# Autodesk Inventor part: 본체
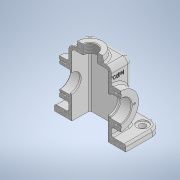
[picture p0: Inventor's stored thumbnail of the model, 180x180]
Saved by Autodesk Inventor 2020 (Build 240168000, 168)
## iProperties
Created: 2021-07
Part Number: 본체
Material: 일반
Document SubType Name: Modeling
Designer: Owner
Density: 1 g/cm^3
Appearance: 기본값
Mass: 278.252 g
Surface Area: 858.264 cm^2
Volume: 278.252 cm^3
Author: Owner
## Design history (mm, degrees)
sketch "스케치1"
  geometry: L1 (34, -34)-(-34, -34); L2 (-34, -34)-(-34, 34); L3 (-34, 34)-(34, 34); L4 (34, 34)-(34, -34); L5 (34, -34)-(-34, 34); L6 (-34, -34)-(34, 34); 1 further point
  constraints: 12 end point, 2 midpoint, 2 parallel, 1 horizontal, 1 perpendicular
  dimensions: "d0" = 68 distance of L2.end L3.end; "d1" = 68 distance of L1.end L2.end
extrude "돌출1" new body sketch "스케치1" distance "d2" = 105; taper "d3" = 0 deg
fillet "모깎기1" dims "d4" = 8
fillet "모깎기2" dims "d5" = 8
feature "쉘1" dims "d6" = 5
node "작업 평면1"
sketch "스케치2"
  geometry: C1 r 20 at (0, 0); 1 further point
  constraints: 1 centre point, 1 coincident
  dimensions: "d8" = 40 diameter of C1
extrude "돌출2" join sketch "스케치2" stored distance "d9" = 105; taper "d10" = 8 deg
sketch "스케치4"
  geometry: L1 (-57, -57)-(57, -57); L2 (57, -57)-(57, 57); L3 (57, 57)-(-57, 57); L4 (-57, 57)-(-57, -57); L5 (-57, -57)-(57, 57); L6 (57, -57)-(-57, 57); L7 (-26, 34)-(26, 34) reference; L8 (-34, -26)-(-34, 26) reference; L9 (26, -34)-(-26, -34) reference; L10 (34, 26)-(34, -26) reference; L11 (-26, 29)-(26, 29) reference; L12 (29, 26)-(29, -26) reference; L13 (26, -29)-(-26, -29) reference; L14 (-29, -26)-(-29, 26) reference; A1 r 8 centre (-26, 26) between (-26, 34) and (-34, 26) reference; A2 r 8 centre (-26, -26) between (-34, -26) and (-26, -34) reference; A3 r 8 centre (26, -26) between (26, -34) and (34, -26) reference; A4 r 8 centre (26, 26) between (34, 26) and (26, 34) reference; A5 r 3 centre (26, 26) between (29, 26) and (26, 29) reference; A6 r 3 centre (26, -26) between (26, -29) and (29, -26) reference; A7 r 3 centre (-26, -26) between (-29, -26) and (-26, -29) reference; A8 r 3 centre (-26, 26) between (-26, 29) and (-29, 26) reference; 1 further point
  constraints: 12 end point, 2 midpoint, 2 parallel, 1 horizontal, 1 perpendicular
  dimensions: "d11" = 114 distance of L3.end L2.end; "d12" = 114 distance of L2.end L1.end
extrude "돌출3" join sketch "스케치4" distance "d13" = 10; taper "d14" = 0 deg
node "작업 평면2"
sketch "스케치6"
  geometry: L1 (26, -97)-(26, 44.872); L2 (83, -97)-(-31, -97) reference; C1 r 28.5 at (26, -45)
  constraints: 2 end point, 1 centre point, 1 point on line, 1 vertical
  dimensions: "d20" = 57 diameter of C1; "d21" = 52 distance from line of L2 C1.centre
extrude "돌출5" join sketch "스케치6" stored distance "d22" = 15; taper "d23" = 0 deg
sketch "스케치7"
  geometry: C1 r 28.5 at (0, 0) reference; C2 r 17.5 at (0, 0); 1 further point
  constraints: 1 centre point, 1 coincident
  dimensions: "d24" = 35 diameter of C2
extrude "돌출6" cut sketch "스케치7" distance "d25" = 17; taper "d26" = 0 deg
sketch "스케치8"
  geometry: C1 r 17.5 at (0, 0) reference; C2 r 15 at (0, 0); 1 further point
  constraints: 1 centre point, 1 coincident
  dimensions: "d27" = 30 diameter of C2
extrude "돌출7" cut sketch "스케치8" distance "d28" = 3; taper "d29" = 0 deg
sketch "스케치9" dims "d30" = 44
  geometry: C1 r 28.5 at (0, 0) reference; C2 r 15 at (0, 0) reference; 3 further points
  constraints: 1 coincident, 1 vertical alignment, 2 other
hole "구멍1" sketch "스케치9" at (0, 22) diameter "d31" = 3.242; stored, may be unused: countersink angle "d35" = 90 deg, drill point angle "d37" = 118 deg; dims "d32" = 8, "d33" = 4, "d34" = 2, "d36" = 10
sketch "스케치10"
  geometry: C1 r 20 at (0, 0) reference; 1 further point
sketch "스케치11"
  geometry: C1 r 20 at (0, 0) reference; 2 further points
  constraints: 1 coincident
hole "구멍2" sketch "스케치11" at (0, 0) diameter "d41" = 22.83494; stored, may be unused: countersink angle "d45" = 90 deg, drill point angle "d47" = 118 deg; dims "d42" = 28.25, "d43" = 4, "d44" = 2, "d46" = 59.3
sketch "스케치12"
  geometry: L1 (43.42, 43.107)-(10, 49); L2 (10, 57)-(10, -57) reference; L3 (0, 57)-(10, 57) reference; 1 further point
  constraints: 2 end point, 1 point on line
  dimensions: "d48" = 8 distance from line of L3 L1.end; "d49" = 100 deg angle of L2 L1
feature "리브1" sketch "스케치12" dims "d50" = 1, "d51" = 10, "d52" = 0, "d53" = 0, "d54" = 1, "d55" = 1
fillet "모깎기3" dims "d56" = 15
sketch "스케치13"
  geometry: C1 r 9 at (-42, -42); A1 r 15 centre (-42, -42) between (-57, -42) and (-42, -57) reference; 1 further point
  constraints: 1 centre point, 1 coincident
  dimensions: "d57" = 18 diameter of C1
extrude "돌출8" cut sketch "스케치13" distance "d58" = 2; taper "d59" = 0 deg
sketch "스케치14"
  geometry: C1 r 9 at (0, 0) reference; C2 r 9 at (0, 0) reference; C3 r 5 at (0, 0); 1 further point
  constraints: 1 centre point, 1 coincident
  dimensions: "d60" = 10 diameter of C3
extrude "돌출9" cut sketch "스케치14" stored distance "d61" = 2; taper "d62" = 0 deg
fillet "모깎기4" dims "d63" = 3
fillet "모깎기5" dims "d64" = 3
fillet "모깎기7" dims "d66" = 3
chamfer "모따기1" distance "d67" = 1; stored, may be unused: second distance "d68" = 2, angle "d69" = 45 deg
chamfer "모따기2" distance "d70" = 1; stored, may be unused: second distance "d71" = 2, angle "d72" = 45 deg
chamfer "모따기3" distance "d73" = 1; stored, may be unused: second distance "d74" = 2, angle "d75" = 45 deg
fillet "모깎기8" dims "d76" = 3
fillet "모깎기9" dims "d77" = 3
fillet "모깎기10" dims "d78" = 3
sketch "스케치15"
  geometry: L1 (6, 18)-(46, 18) reference; L2 (60, -84)-(60, 0) reference; 2 further points
  constraints: 1 other
  dimensions: "d79" = 25 distance from line of L1 point (26, -7); "d80" = 34 distance from line of L2 point (26, -7)
feature "엠보싱1" sketch "스케치15" dims "d6" = 5, "d81" = 0.5, "d82" = 0
node "솔리드1"
pattern_circular "원형 패턴1" dims angle "d39" = 360 deg
mirror "미러1"
mirror "미러2"
mirror "미러3"
mirror "미러4"
node "투영된 루프1"
feature "A9D066F2-1C7D-4E18-AEED-F7BC21143FA4" dims "d41" = 22.83494, "d42" = 28.25, "d43" = 4, "d44" = 2, "d45" = 90 deg, "d46" = 59.3, "d47" = 118 deg
other parameters: "d7" = -115, "d19" = 15
